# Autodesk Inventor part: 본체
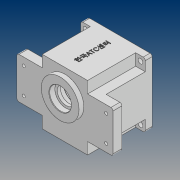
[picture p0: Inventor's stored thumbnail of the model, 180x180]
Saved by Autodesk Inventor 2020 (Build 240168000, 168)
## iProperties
Created: 2020-07
Part Number: 본체
Material: 일반
Document SubType Name: Modeling
Designer: PC312-
Density: 1 g/cm^3
Appearance: 기본값
Author: PC312-
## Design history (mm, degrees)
sketch "스케치1"
  geometry: L1 (47, -47)-(-47, -47); L2 (-47, -47)-(-47, 47); L3 (-47, 47)-(47, 47); L4 (47, 47)-(47, -47); L5 (47, -47)-(-47, 47); L6 (-47, -47)-(47, 47); 1 further point
  constraints: 12 end point, 2 midpoint, 2 parallel, 1 horizontal, 1 perpendicular
  dimensions: "d0" = 94 distance of L2.end L3.end; "d1" = 94 distance of L1.end L2.end
extrude "돌출1" new body sketch "스케치1" distance "d2" = 80; taper "d3" = 0 deg
sketch "스케치2"
  geometry: L1 (70, -30)-(-70, -30); L2 (-70, -30)-(-70, 30); L3 (-70, 30)-(70, 30); L4 (70, 30)-(70, -30); L5 (70, -30)-(-70, 30); L6 (-70, -30)-(70, 30); 1 further point
  constraints: 12 end point, 2 midpoint, 2 parallel, 1 horizontal, 1 perpendicular
  dimensions: "d4" = 140 distance of L2.end L3.end; "d5" = 60 distance of L1.end L2.end
extrude "돌출2" join sketch "스케치2" distance "d6" = 13; taper "d7" = 0 deg
sketch "스케치3"
  geometry: L1 (33, 47)-(47, 47); L2 (47, 47)-(47, 30); L3 (47, 30)-(33, 30); L4 (33, 30)-(33, 47); L5 (47, 47)-(-47, 47) reference; L6 (47, -47)-(47, 47) reference; L7 (0, 0)-(0, -21.053); L8 (0, 0)-(-17.974, 0); L9 (-33, 30)-(-33, 47); L10 (-33, 47)-(-47, 47); L11 (-47, 47)-(-47, 30); L12 (-47, 30)-(-33, 30); L13 (-33, -30)-(-33, -47); L14 (-47, -30)-(-33, -30); L15 (-47, -47)-(-47, -30); L16 (33, -30)-(33, -47); L17 (33, -47)-(47, -47); L18 (47, -47)-(47, -30); L19 (47, -30)-(33, -30); L20 (-33, -47)-(-47, -47); 4 further points
  constraints: 36 end point, 12 symmetric about line, 2 collinear, 2 horizontal, 2 parallel, 1 perpendicular, 1 vertical
  dimensions: "d8" = 33 distance from line of L4 L7.start; "d9" = 30 distance from line of L3 L7.start
extrude "돌출3" cut sketch "스케치3" distance "d10" = 70; taper "d11" = 0 deg
sketch "스케치4"
  geometry: C1 r 27.5 at (0, 11); 1 further point
  constraints: 1 centre point, 1 vertical alignment
  dimensions: "d12" = 55 diameter of C1; "d13" = 11 distance of point (0, 0) C1.centre
extrude "돌출4" join sketch "스케치4" distance "d14" = 7; taper "d15" = 0 deg
sketch "스케치5"
  geometry: 2 further points
  constraints: 1 coincident
hole "구멍1" sketch "스케치5" at (0, 0) diameter "d16" = 80; stored, may be unused: countersink angle "d20" = 90 deg, drill point angle "d22" = 0 deg; dims "d17" = 4, "d18" = 86, "d19" = 9, "d21" = 71
sketch "스케치6"
  geometry: A1 r 21 centre (0, 11) between (8.978, -7.984) and (-8.978, -7.984); A2 r 15 centre (0, -20) between (-8.978, -7.984) and (8.978, -7.984); 1 further point
  constraints: 4 point on circle, 2 centre point, 2 vertical alignment
  dimensions: "d23" = 42 diameter of A1; "d24" = 30 diameter of A2; "d25" = 11 distance of point (0, 0) A1.centre; "d26" = 20 distance of point (0, 0) A2.centre
extrude "돌출5" join sketch "스케치6" distance "d27" = 7; taper "d28" = 0 deg
sketch "스케치7"
  geometry: A1 r 36 centre (0, 0) between (-36, 0) and (36, 0); A2 r 4 centre (-36, 0) between (-36.19, -3.995) and (-36.19, 3.995); A3 r 4 centre (36, 0) between (36.19, 3.995) and (36.19, -3.995); A4 r 40 centre (0, 0) between (-39.279, 7.559) and (-39.279, -7.559) reference; A5 r 3 centre (-36.333, 6.992) between (-39.279, 7.559) and (-35.772, 4.045); A6 r 3 centre (-36.333, -6.992) between (-35.772, -4.045) and (-39.279, -7.559); A7 r 3 centre (36.333, -6.992) between (39.279, -7.559) and (35.772, -4.045); A8 r 3 centre (36.333, 6.992) between (35.772, 4.045) and (39.279, 7.559); 1 further point
  constraints: 26 point on circle, 8 tangent, 7 centre point, 2 horizontal alignment, 1 coincident
  dimensions: "d29" = 72 diameter of A1; "d30" = 8 diameter of A2; "d31" = 8 diameter of A3; "d32" = 6 diameter of A5; "d33" = 6 diameter of A6; "d34" = 6 diameter of A7; "d35" = 6 diameter of A8
extrude "돌출6" join sketch "스케치7" stored distance "d36" = 7; taper "d37" = 0 deg
fillet "모깎기1" dims "d38" = 3
sketch "스케치8"
  geometry: C1 r 11 at (0, -20); A1 r 15 centre (0, -20) between (-11.584, -10.47) and (11.584, -10.47) reference; 1 further point
  constraints: 1 centre point, 1 coincident
  dimensions: "d39" = 22 diameter of C1
extrude "돌출7" cut sketch "스케치8" distance "d40" = 7; taper "d41" = 0 deg
sketch "스케치9"
  geometry: C1 r 11 at (0, 0) reference; C2 r 9.5 at (0, 0); 1 further point
  constraints: 1 centre point, 1 coincident
  dimensions: "d42" = 19 diameter of C2
extrude "돌출8" cut sketch "스케치9" distance "d43" = 3; taper "d44" = 0 deg
sketch "스케치10"
  geometry: A1 r 21 centre (0, 11) between (12.163, -6.119) and (-12.163, -6.119) reference; 2 further points
  constraints: 1 coincident
hole "구멍2" sketch "스케치10" at (0, 11) diameter "d45" = 25; stored, may be unused: countersink angle "d49" = 90 deg, drill point angle "d51" = 0 deg; dims "d46" = 4, "d47" = 35, "d48" = 10, "d50" = 71
sketch "스케치11"
  geometry: C1 r 12.5 at (0, 0) reference; C2 r 16 at (0, 0); 1 further point
  constraints: 1 centre point, 1 coincident
  dimensions: "d52" = 32 diameter of C2
extrude "돌출9" cut sketch "스케치11" distance "d53" = 8.3; taper "d54" = 0 deg
chamfer "모따기1" distance "d55" = 0.8; stored, may be unused: second distance "d56" = 2, angle "d57" = 30 deg
chamfer "모따기2" distance "d58" = 1; stored, may be unused: second distance "d59" = 2, angle "d60" = 30 deg
sketch "스케치13"
  geometry: A1 r 4 centre (-36, 0) between (-36.19, -3.995) and (-36.19, 3.995) reference; A2 r 4 centre (36, 0) between (36.19, 3.995) and (36.19, -3.995) reference; 3 further points
  constraints: 2 coincident
hole "구멍3" sketch "스케치13" at (-36, 0), (36, 0) diameter "d61" = 3.242; stored, may be unused: countersink angle "d65" = 90 deg, drill point angle "d67" = 118 deg; dims "d62" = 7, "d63" = 35, "d64" = 10, "d66" = 9
sketch "스케치14"
  geometry: L1 (-47, 47)-(-47, -47) reference; 2 further points
  dimensions: "d68" = 7 distance from line of L1 point (-40, 40); "d69" = 40 horizontal distance of point (0, 0) point (-40, 40)
hole "구멍4" sketch "스케치14" at (-40, 40) diameter "d70" = 7; stored, may be unused: countersink angle "d74" = 90 deg, drill point angle "d76" = 118 deg; dims "d71" = 7, "d72" = 35, "d73" = 10, "d75" = 9
sketch "스케치15"
  geometry: 3 further points
  constraints: 1 vertical alignment
  dimensions: "d83" = 38 distance of point (-60, -19) point (-60, 19); "d84" = 19 vertical distance of point (0, 0) point (-60, 19); "d85" = 60 horizontal distance of point (0, 0) point (-60, 19)
hole "구멍5" sketch "스케치15" at (-60, 19), (-60, -19) diameter "d86" = 4.5; stored, may be unused: countersink angle "d90" = 82 deg, drill point angle "d92" = 118 deg; dims "d87" = 7, "d88" = 10, "d89" = 5, "d91" = 9
fillet "모깎기2" dims "d93" = 3
fillet "모깎기3" dims "d94" = 3
node "작업 평면1"
sketch "스케치16"
  geometry: L1 (77, 80)-(-11, 80) reference; 2 further points
  constraints: 1 vertical alignment, 1 other
  dimensions: "d96" = 40 distance from line of L1 point (33, 40)
feature "엠보싱1" sketch "스케치16" dims "d0" = 94, "d1" = 94, "d97" = 0.5, "d98" = 0
node "솔리드1"
pattern_linear "직사각형 패턴1" dims "d79" = 80, "d82" = 80
mirror "미러1"
feature "A9D066F2-1C7D-4E18-AEED-F7BC21143FA4" dims "d16" = 80, "d17" = 4, "d18" = 86, "d19" = 9, "d20" = 90 deg, "d21" = 71, "d22" = 0
other parameters: "d95" = 17
